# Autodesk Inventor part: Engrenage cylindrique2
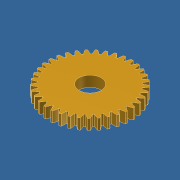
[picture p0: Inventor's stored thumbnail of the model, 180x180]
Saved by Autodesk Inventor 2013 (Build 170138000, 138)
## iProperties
Created: 2011-10
Part Number: Engrenage cylindrique2
Material: Laiton (jaune doux)
Document SubType Name: Modeling
Designer: Laur
Mass: 0.65097 g
Surface Area: 1.97897 cm^2
Volume: 0.076856 cm^3
Density: 8.47 g/cm^3
CustomPartVersion: 1
Author: Laur
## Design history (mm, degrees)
sketch "Sketch1"
  geometry: C1 r 4.78 at (0, 0)
  constraints: 1 centre point
  dimensions: "d0" = 9.56 diameter of C1 (= da_da)
extrude "Extrusion1" new body sketch "Sketch1" distance "d1" = 1.2 (= da_b); taper "d2" = 0 deg
workplane "Work Plane2"
extrude_surface "ExtrusionSrf1" dims "d4" = 10, "d5" = 0
workplane "Work Plane8"
workplane "Work Plane9"
feature "Engrenage cylindrique" dims "da_b" = 1.2, "da_d" = 9.25, "da_aw" = 6, "da_da" = 9.56, "da_df" = 8.435, "da_dw" = 9.25, angle "da_beta" = 0 deg, "da_lefttooth" = 0, "da_righttooth" = 0
sketch "Esquisse3"
  geometry: C1 r 1.25 at (0, 0) reference
extrude "alésage" cut sketch "Esquisse3" stored distance "d49" = 10; taper "d50" = 0 deg
node "Solide1"
node "Corps solides"
node "Corps surfaciques"
sketch "Sketch2"
  geometry: C1 r 4.78 at (0, 0) reference; C2 r 4.625 at (0, 0)
  constraints: 1 centre point, 1 coincident
  dimensions: "d3" = 9.25 diameter of C2 (= da_dw)
body "Srf1"
node "Référence2"
other parameters: "d16" = 6 (= da_aw), "d17" = 0, "d34" = 0.84908 (computed from da_z), "d39" = 0, "d41" = 0, "d43" = 6 (= da_aw), "d46" = 6 (= da_aw), "d47" = 0, "d48" = 0
